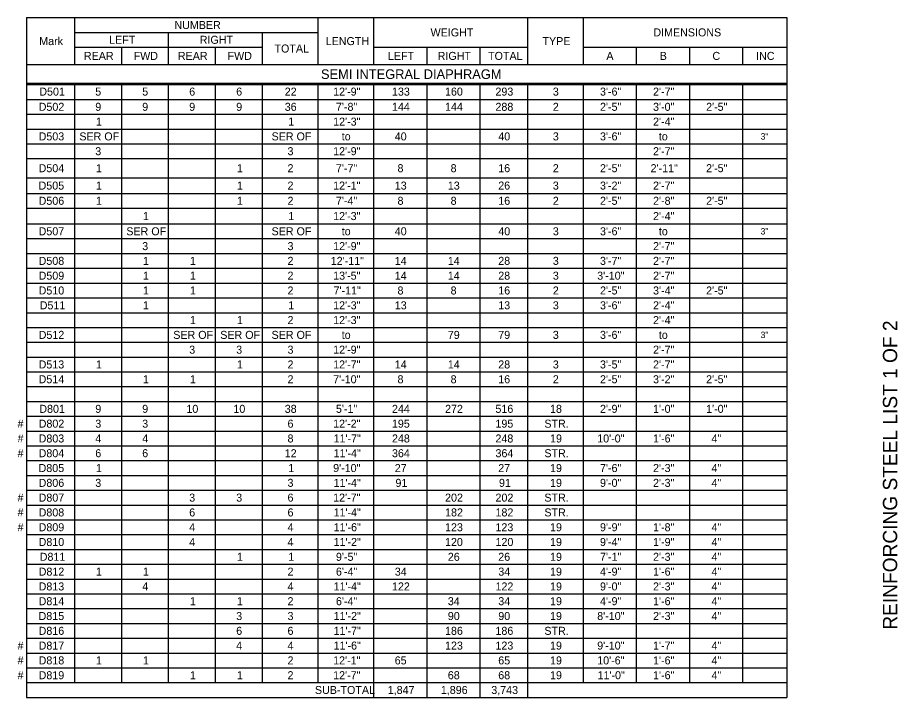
# Model space of a CAD drawing. Extents: x -18.5 to 33.3, y 0.6 to 37.5.
# Drawn here: x 17.04 to 32.43, y 9.51 to 21.4 of the extents above; entities that cross this region are included whole.
import ezdxf

# ---------------------------------------------------------------- set-up
doc = ezdxf.new("R2010")
doc.units = 0
doc.layers.add('BR_X_Beam_Centerline', color=7, linetype='Continuous')
doc.layers.add('Default', color=7, linetype='Continuous')

msp = doc.modelspace()

# ---------------------------------------------------------------- linework, layer by layer
at = {"layer": 'Default'}
for p, q in [((17.194, 21.396), (30.493, 21.396)), ((17.194, 21.396), (17.194, 20.229)), ((18.031, 21.396), (18.031, 20.574)), ((22.291, 21.396), (22.291, 20.574)), ((23.265, 21.396), (23.265, 20.574)), ((25.959, 21.396), (25.959, 20.574)), ((26.933, 21.396), (26.933, 20.574)), ((30.493, 21.396), (30.493, 20.229)), ((18.031, 21.137), (22.291, 21.137)), ((19.674, 21.137), (19.674, 20.574)), ((21.318, 21.137), (21.318, 20.574)), ((18.031, 20.878), (21.318, 20.878)), ((18.853, 20.878), (18.853, 20.574)), ((20.496, 20.878), (20.496, 20.574)), ((23.265, 20.878), (25.959, 20.878)), ((24.194, 20.878), (24.194, 20.574)), ((25.122, 20.878), (25.122, 20.574)), ((26.933, 20.878), (30.493, 20.878)), ((27.861, 20.878), (27.861, 20.574)), ((28.789, 20.878), (28.789, 20.574)), ((29.717, 20.878), (29.717, 20.574)), ((17.194, 20.574), (30.493, 20.574)), ((17.194, 20.249), (30.493, 20.249)), ((17.194, 20.249), (17.194, 9.511)), ((17.194, 20.229), (30.493, 20.229)), ((18.031, 20.229), (18.031, 9.77)), ((18.853, 20.229), (18.853, 9.77)), ((19.674, 20.229), (19.674, 9.77)), ((20.496, 20.229), (20.496, 9.77)), ((21.318, 20.249), (21.318, 9.77)), ((22.291, 20.229), (22.291, 9.77)), ((23.265, 20.229), (23.265, 9.511)), ((24.194, 20.229), (24.194, 9.511)), ((25.122, 20.249), (25.122, 9.511)), ((25.959, 20.229), (25.959, 9.511)), ((26.933, 20.229), (26.933, 9.77)), ((27.861, 20.229), (27.861, 9.77)), ((28.789, 20.229), (28.789, 9.77)), ((29.717, 20.249), (29.717, 9.77)), ((30.493, 20.249), (30.493, 9.511)), ((17.194, 19.965), (30.493, 19.965)), ((17.194, 19.707), (30.493, 19.707)), ((17.194, 19.448), (30.493, 19.448)), ((17.194, 19.189), (30.493, 19.189)), ((17.194, 18.931), (30.493, 18.931)), ((17.194, 18.596), (30.493, 18.596)), ((17.194, 18.322), (30.493, 18.322)), ((17.194, 18.063), (30.493, 18.063)), ((17.194, 17.789), (30.493, 17.789)), ((17.194, 17.531), (30.493, 17.531)), ((17.194, 17.272), (30.493, 17.272)), ((17.194, 17.013), (30.493, 17.013)), ((17.194, 16.755), (30.493, 16.755)), ((17.194, 16.496), (30.493, 16.496)), ((17.194, 16.237), (30.493, 16.237)), ((17.194, 15.978), (30.493, 15.978)), ((17.194, 15.72), (30.493, 15.72)), ((17.194, 15.461), (30.493, 15.461)), ((17.194, 15.202), (30.493, 15.202)), ((17.194, 14.944), (30.493, 14.944)), ((17.194, 14.685), (30.493, 14.685)), ((17.194, 14.426), (30.493, 14.426)), ((17.194, 14.168), (30.493, 14.168)), ((17.194, 13.909), (30.493, 13.909)), ((17.194, 13.65), (30.493, 13.65)), ((17.194, 13.392), (30.493, 13.392)), ((17.194, 13.133), (30.493, 13.133)), ((17.194, 12.874), (30.493, 12.874)), ((17.194, 12.616), (30.493, 12.616)), ((17.194, 12.357), (30.493, 12.357)), ((17.194, 12.098), (30.493, 12.098)), ((17.194, 11.84), (30.493, 11.84)), ((17.194, 11.581), (30.493, 11.581)), ((17.194, 11.322), (30.493, 11.322)), ((17.194, 11.063), (30.493, 11.063)), ((17.194, 10.805), (30.493, 10.805)), ((17.194, 10.546), (30.493, 10.546)), ((17.194, 10.287), (30.493, 10.287)), ((17.194, 10.029), (30.493, 10.029)), ((17.194, 9.77), (30.493, 9.77)), ((17.194, 9.511), (30.494, 9.511))]:
    msp.add_line(p, q, dxfattribs=at)

# ---------------------------------------------------------------- texts
at = {"layer": 'BR_X_Beam_Centerline'}
for s, height, p in [('NUMBER', 0.14, (19.781, 21.196)), ('WEIGHT', 0.14, (24.262, 21.067)), ('DIMENSIONS', 0.14, (28.16, 21.067)), ('Mark', 0.14, (17.417, 20.915)), ('LEFT', 0.14, (18.639, 20.938)), ('RIGHT', 0.14, (20.224, 20.938)), ('LENGTH', 0.14, (22.428, 20.915)), ('TYPE', 0.14, (26.22, 20.915)), ('REAR', 0.14, (18.198, 20.656)), ('FWD', 0.14, (19.068, 20.656)), ('REAR', 0.14, (19.842, 20.656)), ('FWD', 0.14, (20.711, 20.656)), ('TOTAL', 0.14, (21.532, 20.785)), ('LEFT', 0.14, (23.516, 20.656)), ('RIGHT', 0.14, (24.386, 20.656)), ('TOTAL', 0.14, (25.268, 20.656)), ('A', 0.14, (27.338, 20.656)), ('B', 0.14, (28.271, 20.656)), ('C', 0.14, (29.193, 20.656)), ('INC', 0.14, (29.957, 20.656)), ('SEMI INTEGRAL DIAPHRAGM', 0.16799, (22.345, 20.323)), ('D501', 0.14, (17.418, 20.032)), ('5', 0.14, (18.396, 20.032)), ('5', 0.14, (19.218, 20.032)), ('6', 0.14, (20.04, 20.032)), ('6', 0.14, (20.862, 20.032)), ('22', 0.14, (21.711, 20.032)), ('12\'-9"', 0.14, (22.558, 20.032)), ('133', 0.14, (23.587, 20.032)), ('160', 0.14, (24.515, 20.032)), ('293', 0.14, (25.397, 20.032)), ('3', 0.14, (26.401, 20.032)), ('3\'-6"', 0.14, (27.226, 20.032)), ('2\'-7"', 0.14, (28.154, 20.032)), ('D502', 0.14, (17.407, 19.766)), ('9', 0.14, (18.397, 19.766)), ('9', 0.14, (19.218, 19.766)), ('9', 0.14, (20.04, 19.766)), ('9', 0.14, (20.862, 19.766)), ('36', 0.14, (21.711, 19.766)), ('7\'-8"', 0.14, (22.607, 19.766)), ('144', 0.14, (23.587, 19.766)), ('144', 0.14, (24.515, 19.766)), ('288', 0.14, (25.397, 19.766)), ('2', 0.14, (26.401, 19.766)), ('2\'-5"', 0.14, (27.226, 19.766)), ('3\'-0"', 0.14, (28.154, 19.766)), ('2\'-5"', 0.14, (29.082, 19.766)), ('1', 0.14, (18.409, 19.507)), ('1', 0.14, (21.772, 19.507)), ('12\'-3"', 0.14, (22.558, 19.507)), ('2\'-4"', 0.14, (28.154, 19.507)), ('D503', 0.14, (17.406, 19.249)), ('SER OF', 0.14, (18.118, 19.249)), ('SER OF', 0.14, (21.481, 19.249)), ('to', 0.14, (22.708, 19.249)), ('40', 0.14, (23.636, 19.249)), ('40', 0.14, (25.447, 19.249)), ('3', 0.14, (26.401, 19.249)), ('3\'-6"', 0.14, (27.226, 19.249)), ('to', 0.14, (28.255, 19.249)), ('3"', 0.112, (30.036, 19.263)), ('3', 0.14, (18.397, 18.99)), ('3', 0.14, (21.76, 18.99)), ('12\'-9"', 0.14, (22.558, 18.99)), ('2\'-7"', 0.14, (28.154, 18.99)), ('D504', 0.14, (17.406, 18.693)), ('1', 0.14, (18.409, 18.693)), ('1', 0.14, (20.874, 18.693)), ('2', 0.14, (21.76, 18.693)), ('7\'-7"', 0.14, (22.607, 18.693)), ('8', 0.14, (23.684, 18.693)), ('8', 0.14, (24.613, 18.693)), ('16', 0.14, (25.446, 18.693)), ('2', 0.14, (26.401, 18.693)), ('2\'-5"', 0.14, (27.226, 18.693)), ('2\'-11"', 0.14, (28.111, 18.693)), ('2\'-5"', 0.14, (29.082, 18.693)), ('D505', 0.14, (17.405, 18.389)), ('1', 0.14, (18.409, 18.389)), ('1', 0.14, (20.874, 18.389)), ('2', 0.14, (21.76, 18.389)), ('12\'-1"', 0.14, (22.558, 18.389)), ('13', 0.14, (23.636, 18.389)), ('13', 0.14, (24.564, 18.389)), ('26', 0.14, (25.446, 18.389)), ('3', 0.14, (26.401, 18.389)), ('3\'-2"', 0.14, (27.226, 18.389)), ('2\'-7"', 0.14, (28.154, 18.389)), ('D506', 0.14, (17.406, 18.123)), ('1', 0.14, (18.409, 18.123)), ('1', 0.14, (20.874, 18.123)), ('2', 0.14, (21.76, 18.123)), ('7\'-4"', 0.14, (22.607, 18.123)), ('8', 0.14, (23.684, 18.123)), ('8', 0.14, (24.613, 18.123)), ('16', 0.14, (25.446, 18.123)), ('2', 0.14, (26.401, 18.123)), ('2\'-5"', 0.14, (27.226, 18.123)), ('2\'-8"', 0.14, (28.154, 18.123)), ('2\'-5"', 0.14, (29.082, 18.123)), ('1', 0.14, (19.231, 17.856)), ('1', 0.14, (21.772, 17.856)), ('12\'-3"', 0.14, (22.558, 17.856)), ('2\'-4"', 0.14, (28.154, 17.856)), ('D507', 0.14, (17.406, 17.59)), ('SER OF', 0.14, (18.94, 17.59)), ('SER OF', 0.14, (21.481, 17.59)), ('to', 0.14, (22.708, 17.59)), ('40', 0.14, (23.636, 17.59)), ('40', 0.14, (25.447, 17.59)), ('3', 0.14, (26.401, 17.59)), ('3\'-6"', 0.14, (27.226, 17.59)), ('to', 0.14, (28.255, 17.59)), ('3"', 0.112, (30.036, 17.604)), ('3', 0.14, (19.218, 17.331)), ('3', 0.14, (21.76, 17.331)), ('12\'-9"', 0.14, (22.558, 17.331)), ('2\'-7"', 0.14, (28.154, 17.331)), ('D508', 0.14, (17.406, 17.073)), ('1', 0.14, (19.231, 17.073)), ('1', 0.14, (20.052, 17.073)), ('2', 0.14, (21.76, 17.073)), ('12\'-11"', 0.14, (22.516, 17.073)), ('14', 0.14, (23.636, 17.073)), ('14', 0.14, (24.564, 17.073)), ('28', 0.14, (25.446, 17.073)), ('3', 0.14, (26.401, 17.073)), ('3\'-7"', 0.14, (27.226, 17.073)), ('2\'-7"', 0.14, (28.154, 17.073)), ('D509', 0.14, (17.406, 16.814)), ('1', 0.14, (19.231, 16.814)), ('1', 0.14, (20.052, 16.814)), ('2', 0.14, (21.76, 16.814)), ('13\'-5"', 0.14, (22.558, 16.814)), ('14', 0.14, (23.636, 16.814)), ('14', 0.14, (24.564, 16.814)), ('28', 0.14, (25.446, 16.814)), ('3', 0.14, (26.401, 16.814)), ('3\'-10"', 0.14, (27.177, 16.814)), ('2\'-7"', 0.14, (28.154, 16.814)), ('D510', 0.14, (17.406, 16.555)), ('1', 0.14, (19.231, 16.555)), ('1', 0.14, (20.052, 16.555)), ('2', 0.14, (21.76, 16.555)), ('7\'-11"', 0.14, (22.565, 16.555)), ('8', 0.14, (23.684, 16.555)), ('8', 0.14, (24.613, 16.555)), ('16', 0.14, (25.446, 16.555)), ('2', 0.14, (26.401, 16.555)), ('2\'-5"', 0.14, (27.226, 16.555)), ('3\'-4"', 0.14, (28.154, 16.555)), ('2\'-5"', 0.14, (29.082, 16.555)), ('D511', 0.14, (17.425, 16.296)), ('1', 0.14, (19.231, 16.296)), ('1', 0.14, (21.772, 16.296)), ('12\'-3"', 0.14, (22.558, 16.296)), ('13', 0.14, (23.636, 16.296)), ('13', 0.14, (25.446, 16.296)), ('3', 0.14, (26.401, 16.296)), ('3\'-6"', 0.14, (27.226, 16.296)), ('2\'-4"', 0.14, (28.154, 16.296)), ('1', 0.14, (20.052, 16.038)), ('1', 0.14, (20.874, 16.038)), ('2', 0.14, (21.76, 16.038)), ('12\'-3"', 0.14, (22.558, 16.038)), ('2\'-4"', 0.14, (28.154, 16.038)), ('D512', 0.14, (17.407, 15.779)), ('SER OF', 0.14, (19.761, 15.779)), ('SER OF', 0.14, (20.583, 15.779)), ('SER OF', 0.14, (21.481, 15.779)), ('to', 0.14, (22.708, 15.779)), ('79', 0.14, (24.564, 15.779)), ('79', 0.14, (25.446, 15.779)), ('3', 0.14, (26.401, 15.779)), ('3\'-6"', 0.14, (27.226, 15.779)), ('to', 0.14, (28.255, 15.779)), ('3"', 0.112, (30.036, 15.793)), ('3', 0.14, (20.04, 15.52)), ('3', 0.14, (20.862, 15.52)), ('3', 0.14, (21.76, 15.52)), ('12\'-9"', 0.14, (22.558, 15.52)), ('2\'-7"', 0.14, (28.154, 15.52)), ('D513', 0.14, (17.406, 15.262)), ('1', 0.14, (18.409, 15.262)), ('1', 0.14, (20.874, 15.262)), ('2', 0.14, (21.76, 15.262)), ('12\'-7"', 0.14, (22.558, 15.262)), ('14', 0.14, (23.636, 15.262)), ('14', 0.14, (24.564, 15.262)), ('28', 0.14, (25.446, 15.262)), ('3', 0.14, (26.401, 15.262)), ('3\'-5"', 0.14, (27.226, 15.262)), ('2\'-7"', 0.14, (28.154, 15.262)), ('D514', 0.14, (17.406, 15.003)), ('1', 0.14, (19.231, 15.003)), ('1', 0.14, (20.052, 15.003)), ('2', 0.14, (21.76, 15.003)), ('7\'-10"', 0.14, (22.558, 15.003)), ('8', 0.14, (23.684, 15.003)), ('8', 0.14, (24.613, 15.003)), ('16', 0.14, (25.446, 15.003)), ('2', 0.14, (26.401, 15.003)), ('2\'-5"', 0.14, (27.226, 15.003)), ('3\'-2"', 0.14, (28.154, 15.003)), ('2\'-5"', 0.14, (29.082, 15.003)), ('D801', 0.14, (17.418, 14.486)), ('9', 0.14, (18.397, 14.486)), ('9', 0.14, (19.218, 14.486)), ('10', 0.14, (19.991, 14.486)), ('10', 0.14, (20.813, 14.486)), ('38', 0.14, (21.711, 14.486)), ('5\'-1"', 0.14, (22.607, 14.486)), ('244', 0.14, (23.587, 14.486)), ('272', 0.14, (24.516, 14.486)), ('516', 0.14, (25.397, 14.486)), ('18', 0.14, (26.352, 14.486)), ('2\'-9"', 0.14, (27.226, 14.486)), ('1\'-0"', 0.14, (28.154, 14.486)), ('1\'-0"', 0.14, (29.082, 14.486)), ('#', 0.14, (17.037, 14.227)), ('D802', 0.14, (17.407, 14.227)), ('3', 0.14, (18.397, 14.227)), ('3', 0.14, (19.218, 14.227)), ('6', 0.14, (21.76, 14.227)), ('12\'-2"', 0.14, (22.558, 14.227)), ('195', 0.14, (23.586, 14.227)), ('195', 0.14, (25.397, 14.227)), ('STR.', 0.14, (26.253, 14.227)), ('#', 0.14, (17.037, 13.968)), ('D803', 0.14, (17.406, 13.968)), ('4', 0.14, (18.397, 13.968)), ('4', 0.14, (19.219, 13.968)), ('8', 0.14, (21.76, 13.968)), ('11\'-7"', 0.14, (22.565, 13.968)), ('248', 0.14, (23.587, 13.968)), ('248', 0.14, (25.397, 13.968)), ('19', 0.14, (26.352, 13.968)), ('10\'-0"', 0.14, (27.177, 13.968)), ('1\'-6"', 0.14, (28.154, 13.968)), ('4"', 0.14, (29.177, 13.968)), ('D804', 0.14, (17.406, 13.71)), ('6', 0.14, (18.397, 13.71)), ('6', 0.14, (19.218, 13.71)), ('12', 0.14, (21.711, 13.71)), ('364', 0.14, (23.587, 13.71)), ('364', 0.14, (25.398, 13.71)), ('STR.', 0.14, (26.253, 13.71)), ('#', 0.14, (17.037, 13.71)), ('11\'-4"', 0.14, (22.565, 13.71)), ('D805', 0.14, (17.405, 13.451)), ('1', 0.14, (18.409, 13.451)), ('1', 0.14, (21.772, 13.451)), ('9\'-10"', 0.14, (22.558, 13.451)), ('27', 0.14, (23.636, 13.451)), ('27', 0.14, (25.446, 13.451)), ('19', 0.14, (26.352, 13.451)), ('7\'-6"', 0.14, (27.226, 13.451)), ('2\'-3"', 0.14, (28.154, 13.451)), ('4"', 0.14, (29.177, 13.451)), ('D806', 0.14, (17.406, 13.192)), ('3', 0.14, (18.397, 13.192)), ('3', 0.14, (21.76, 13.192)), ('11\'-4"', 0.14, (22.565, 13.192)), ('91', 0.14, (23.648, 13.192)), ('91', 0.14, (25.459, 13.192)), ('19', 0.14, (26.352, 13.192)), ('9\'-0"', 0.14, (27.226, 13.192)), ('2\'-3"', 0.14, (28.154, 13.192)), ('4"', 0.14, (29.177, 13.192)), ('#', 0.14, (17.037, 12.934)), ('D807', 0.14, (17.406, 12.934)), ('3', 0.14, (20.04, 12.934)), ('3', 0.14, (20.862, 12.934)), ('6', 0.14, (21.76, 12.934)), ('12\'-7"', 0.14, (22.558, 12.934)), ('202', 0.14, (24.516, 12.934)), ('202', 0.14, (25.398, 12.934)), ('STR.', 0.14, (26.253, 12.934)), ('#', 0.14, (17.037, 12.675)), ('D808', 0.14, (17.406, 12.675)), ('6', 0.14, (20.04, 12.675)), ('6', 0.14, (21.76, 12.675)), ('11\'-4"', 0.14, (22.565, 12.675)), ('182', 0.14, (24.516, 12.675)), ('182', 0.14, (25.398, 12.675)), ('STR.', 0.14, (26.253, 12.675)), ('#', 0.14, (17.037, 12.416)), ('D809', 0.14, (17.406, 12.416)), ('4', 0.14, (20.04, 12.416)), ('4', 0.14, (21.76, 12.416)), ('11\'-6"', 0.14, (22.565, 12.416)), ('123', 0.14, (24.515, 12.416)), ('123', 0.14, (25.397, 12.416)), ('19', 0.14, (26.352, 12.416)), ('9\'-9"', 0.14, (27.226, 12.416)), ('1\'-8"', 0.14, (28.154, 12.416)), ('4"', 0.14, (29.177, 12.416)), ('D810', 0.14, (17.406, 12.158)), ('4', 0.14, (20.04, 12.158)), ('4', 0.14, (21.76, 12.158)), ('11\'-2"', 0.14, (22.565, 12.158)), ('120', 0.14, (24.515, 12.158)), ('120', 0.14, (25.398, 12.158)), ('19', 0.14, (26.352, 12.158)), ('9\'-4"', 0.14, (27.226, 12.158)), ('1\'-9"', 0.14, (28.154, 12.158)), ('4"', 0.14, (29.177, 12.158)), ('D811', 0.14, (17.425, 11.899)), ('1', 0.14, (20.874, 11.899)), ('1', 0.14, (21.772, 11.899)), ('9\'-5"', 0.14, (22.607, 11.899)), ('26', 0.14, (24.564, 11.899)), ('26', 0.14, (25.446, 11.899)), ('19', 0.14, (26.352, 11.899)), ('7\'-1"', 0.14, (27.226, 11.899)), ('2\'-3"', 0.14, (28.154, 11.899)), ('4"', 0.14, (29.177, 11.899)), ('D812', 0.14, (17.407, 11.64)), ('1', 0.14, (18.409, 11.64)), ('1', 0.14, (19.231, 11.64)), ('2', 0.14, (21.76, 11.64)), ('6\'-4"', 0.14, (22.607, 11.64)), ('34', 0.14, (23.636, 11.64)), ('34', 0.14, (25.447, 11.64)), ('19', 0.14, (26.352, 11.64)), ('4\'-9"', 0.14, (27.226, 11.64)), ('1\'-6"', 0.14, (28.154, 11.64)), ('4"', 0.14, (29.177, 11.64)), ('D813', 0.14, (17.406, 11.381)), ('4', 0.14, (19.219, 11.381)), ('4', 0.14, (21.76, 11.381)), ('11\'-4"', 0.14, (22.565, 11.381)), ('122', 0.14, (23.587, 11.381)), ('122', 0.14, (25.398, 11.381)), ('19', 0.14, (26.352, 11.381)), ('9\'-0"', 0.14, (27.226, 11.381)), ('2\'-3"', 0.14, (28.154, 11.381)), ('4"', 0.14, (29.177, 11.381)), ('D814', 0.14, (17.406, 11.123)), ('1', 0.14, (20.052, 11.123)), ('1', 0.14, (20.874, 11.123)), ('2', 0.14, (21.76, 11.123)), ('6\'-4"', 0.14, (22.607, 11.123)), ('34', 0.14, (24.564, 11.123)), ('34', 0.14, (25.447, 11.123)), ('19', 0.14, (26.352, 11.123)), ('4\'-9"', 0.14, (27.226, 11.123)), ('1\'-6"', 0.14, (28.154, 11.123)), ('4"', 0.14, (29.177, 11.123)), ('D815', 0.14, (17.405, 10.864)), ('3', 0.14, (20.862, 10.864)), ('3', 0.14, (21.76, 10.864)), ('11\'-2"', 0.14, (22.565, 10.864)), ('90', 0.14, (24.564, 10.864)), ('90', 0.14, (25.447, 10.864)), ('19', 0.14, (26.352, 10.864)), ('8\'-10"', 0.14, (27.177, 10.864)), ('2\'-3"', 0.14, (28.154, 10.864)), ('4"', 0.14, (29.177, 10.864)), ('D816', 0.14, (17.406, 10.605)), ('6', 0.14, (20.862, 10.605)), ('6', 0.14, (21.76, 10.605)), ('11\'-7"', 0.14, (22.565, 10.605)), ('186', 0.14, (24.515, 10.605)), ('186', 0.14, (25.397, 10.605)), ('STR.', 0.14, (26.253, 10.605)), ('#', 0.14, (17.037, 10.347)), ('D817', 0.14, (17.406, 10.347)), ('4', 0.14, (20.862, 10.347)), ('4', 0.14, (21.76, 10.347)), ('11\'-6"', 0.14, (22.565, 10.347)), ('123', 0.14, (24.515, 10.347)), ('123', 0.14, (25.397, 10.347)), ('19', 0.14, (26.352, 10.347)), ('9\'-10"', 0.14, (27.177, 10.347)), ('1\'-7"', 0.14, (28.154, 10.347)), ('4"', 0.14, (29.177, 10.347)), ('#', 0.14, (17.037, 10.088)), ('D818', 0.14, (17.406, 10.088)), ('1', 0.14, (18.409, 10.088)), ('1', 0.14, (19.231, 10.088)), ('2', 0.14, (21.76, 10.088)), ('12\'-1"', 0.14, (22.558, 10.088)), ('65', 0.14, (23.635, 10.088)), ('65', 0.14, (25.446, 10.088)), ('19', 0.14, (26.352, 10.088)), ('10\'-6"', 0.14, (27.177, 10.088)), ('1\'-6"', 0.14, (28.154, 10.088)), ('4"', 0.14, (29.177, 10.088)), ('#', 0.14, (17.037, 9.829)), ('D819', 0.14, (17.406, 9.829)), ('1', 0.14, (20.052, 9.829)), ('1', 0.14, (20.874, 9.829)), ('2', 0.14, (21.76, 9.829)), ('12\'-7"', 0.14, (22.558, 9.829)), ('68', 0.14, (24.564, 9.829)), ('68', 0.14, (25.446, 9.829)), ('19', 0.14, (26.352, 9.829)), ('11\'-0"', 0.14, (27.183, 9.829)), ('1\'-6"', 0.14, (28.154, 9.829)), ('4"', 0.14, (29.177, 9.829)), ('SUB-TOTAL', 0.14, (22.239, 9.571)), ('1,847', 0.14, (23.513, 9.571)), ('1,896', 0.14, (24.442, 9.571)), ('3,743', 0.14, (25.324, 9.571))]:
    msp.add_text(s, height=height, dxfattribs=at).set_placement(p)
msp.add_text('REINFORCING STEEL LIST 1 OF 2', height=0.25, rotation=90, dxfattribs=at).set_placement((32.425, 10.695))

doc.saveas('drawing.dxf')
